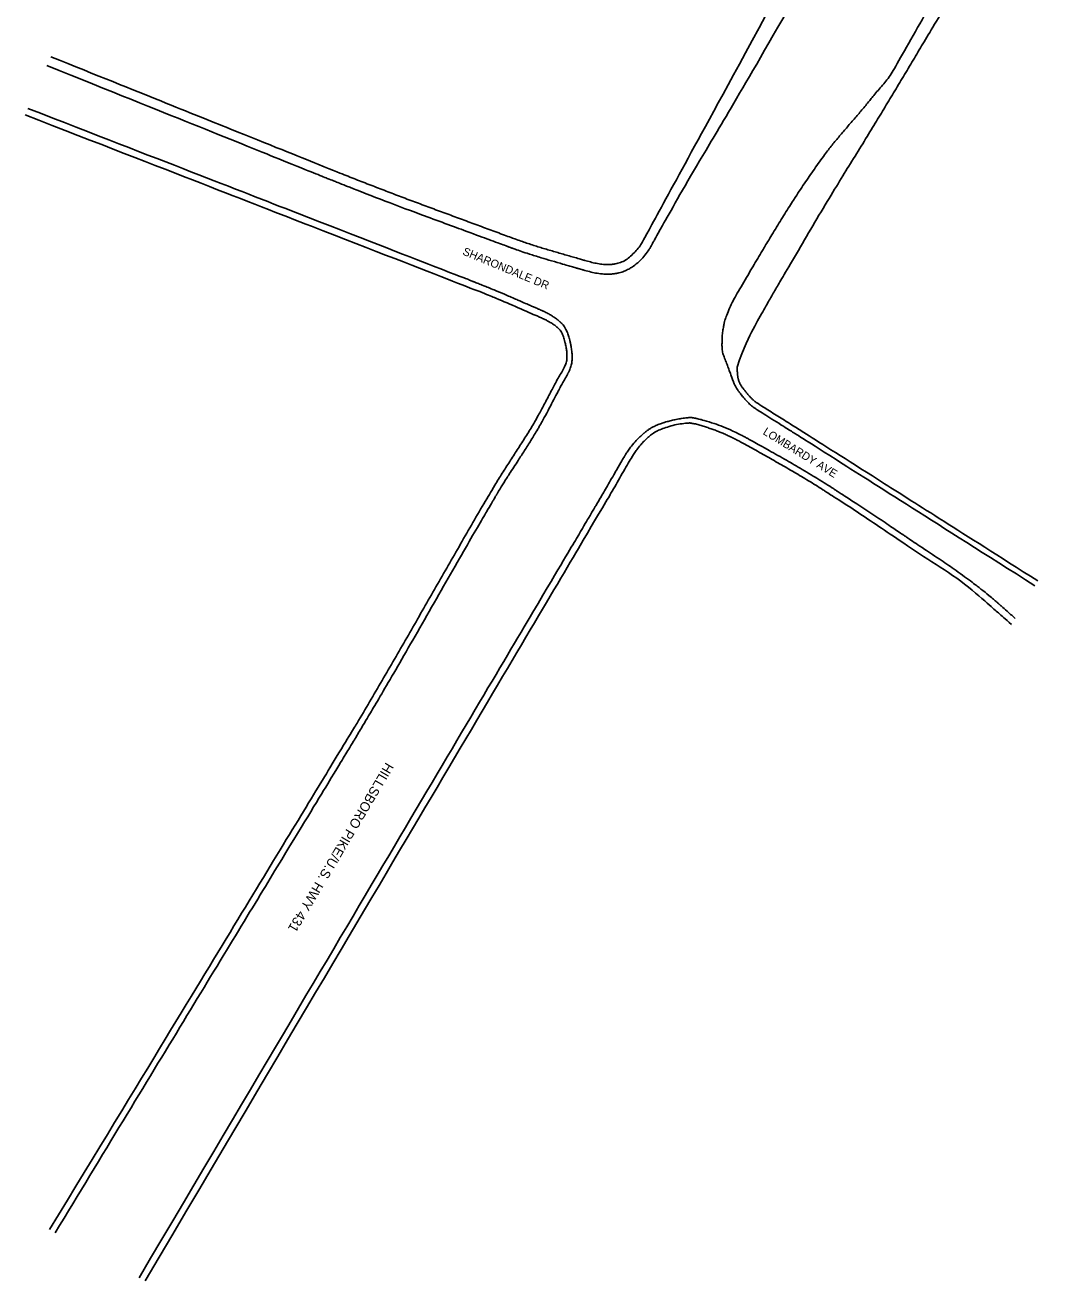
# Model space of a CAD drawing. Extents: x 1729281 to 1732101, y 650763 to 653805.
# Drawn here: x 1729590 to 1730235, y 651061 to 651845 of the extents above; entities that cross this region are included whole.
import ezdxf

# ---------------------------------------------------------------- set-up
doc = ezdxf.new("R2010")
doc.units = 0
for name, color, linetype in [('SURVEY - ROADSIDE BARRIERS with Text', 7, 'Continuous'), ('SURVEY - TRANSPORTATION - Roads', 7, 'Continuous'), ('SURVEY - TRANSPORTATION - Roads Text', 7, 'Continuous')]:
    doc.layers.add(name, color=color, linetype=linetype)

msp = doc.modelspace()

# ---------------------------------------------------------------- linework, layer by layer
at = {"layer": 'SURVEY - ROADSIDE BARRIERS with Text'}
for points in [[(1729607.28, 652582.79), (1729656.5, 652570.21), (1729705.61, 652557.15), (1729754.69, 652544), (1729803.78, 652530.84), (1729852.75, 652517.23), (1729901.76, 652503.78), (1729923.26, 652497.88), (1729944.71, 652491.85), (1729966.14, 652485.64), (1729976.27, 652482.71), (1729986.17, 652479.02), (1729995.91, 652474.96), (1730000.8, 652472.93), (1730005.64, 652470.81), (1730010.45, 652468.61), (1730015.28, 652466.4), (1730020.1, 652464.18), (1730024.89, 652461.88), (1730029.11, 652459.85), (1730033.28, 652457.72), (1730037.41, 652455.5), (1730041.51, 652453.29), (1730045.54, 652450.96), (1730049.52, 652448.54), (1730053.51, 652446.11), (1730057.45, 652443.62), (1730061.35, 652441.05), (1730065.28, 652438.46), (1730069.16, 652435.81), (1730073.02, 652433.1), (1730076.79, 652430.46), (1730080.48, 652427.72), (1730084.14, 652424.92), (1730087.78, 652422.14), (1730091.29, 652419.23), (1730094.75, 652416.24), (1730098.22, 652413.26), (1730101.53, 652410.13), (1730104.8, 652406.93), (1730108.11, 652403.69), (1730111.24, 652400.33), (1730114.27, 652396.83), (1730120.69, 652389.39), (1730126.62, 652381.63), (1730132.24, 652373.56), (1730137.84, 652365.51), (1730142.91, 652357.23), (1730147.82, 652348.73), (1730153.25, 652339.33), (1730158.14, 652329.79), (1730162.46, 652319.78), (1730167.07, 652309.1), (1730170.27, 652298.17), (1730173.35, 652286.9), (1730176.3, 652276.14), (1730179.69, 652265.38), (1730179.43, 652254.38), (1730179.05, 652238.66), (1730177.83, 652222.9), (1730176.7, 652207.18), (1730176.17, 652199.67), (1730175.69, 652192.16), (1730174.92, 652184.66), (1730172.45, 652160.83), (1730166.43, 652137.56), (1730159.58, 652114.52), (1730154.45, 652097.26), (1730149.17, 652080.18), (1730142.79, 652063.41), (1730133.99, 652040.24), (1730124.7, 652017.28), (1730116.01, 651994.07), (1730113.25, 651986.71), (1730110.5, 651979.34), (1730107.76, 651971.96), (1730105.02, 651964.59), (1730102.42, 651957.16), (1730099.69, 651949.77), (1730094.24, 651935.05), (1730088.32, 651920.44), (1730081.08, 651906.51), (1730070.13, 651885.43), (1730059.18, 651864.34), (1730048.23, 651843.25)], [(1730034.37, 651631.27), (1730038.78, 651643.98), (1730044.83, 651656.11), (1730051.49, 651667.81), (1730055.5, 651674.84), (1730059.55, 651681.84), (1730063.66, 651688.81), (1730073.99, 651706.34), (1730084.2, 651723.94), (1730094.73, 651741.35), (1730102.26, 651753.8), (1730110.03, 651766.09), (1730117.59, 651778.52), (1730123.75, 651788.66), (1730129.9, 651798.79), (1730136.01, 651808.95), (1730142.12, 651819.12), (1730148.15, 651829.33), (1730154.25, 651839.5), (1730163.39, 651854.75), (1730172.66, 651869.93), (1730181.9, 651885.14), (1730184.98, 651890.21), (1730188.11, 651895.24), (1730191.34, 651900.22), (1730194.52, 651905.11), (1730198.02, 651909.76), (1730201.62, 651914.35), (1730203.42, 651916.64), (1730205.27, 651918.89), (1730207.07, 651921.18), (1730208.87, 651923.48), (1730210.64, 651925.79), (1730212.41, 651928.1), (1730216.77, 651933.79), (1730220.59, 651939.87), (1730224.91, 651945.61), (1730227.32, 651948.8), (1730230.05, 651951.72), (1730233.01, 651954.44), (1730234.5, 651955.81), (1730236.07, 651957.04), (1730237.69, 651958.25), (1730239.34, 651959.47), (1730241.02, 651960.62), (1730242.77, 651961.69), (1730245.89, 651963.61), (1730249.11, 651965.23), (1730252.5, 651966.62), (1730255.86, 651967.99), (1730259.26, 651969.05), (1730262.77, 651969.91), (1730269.63, 651971.61), (1730276.5, 651972.86), (1730283.49, 651973.85), (1730291.08, 651974.92), (1730298.75, 651975.53), (1730306.35, 651975.28), (1730313.17, 651975.04), (1730320.01, 651974.17), (1730326.7, 651972.42), (1730334.32, 651970.42), (1730341.67, 651968), (1730349.21, 651965.98), (1730366.07, 651961.48), (1730382.84, 651957.15), (1730399.99, 651953.25), (1730412.36, 651950.43), (1730424.92, 651948.91), (1730437.49, 651948.6), (1730449.02, 651948.32), (1730460.62, 651948.91), (1730472.14, 651950.03), (1730480.98, 651950.89), (1730489.79, 651951.8), (1730498.56, 651953.25), (1730508.4, 651954.87), (1730518.17, 651956.64), (1730527.85, 651958.97), (1730538.72, 651961.58), (1730549.49, 651964.58), (1730560.35, 651967.19), (1730596.39, 651975.85), (1730632.48, 651984.17), (1730668.64, 651992.36), (1730684.27, 651995.91), (1730699.92, 651999.04), (1730715.78, 652001.66), (1730733.43, 652004.57), (1730751.19, 652006.36), (1730769, 652006.66), (1730780.51, 652006.85), (1730792.01, 652007.04), (1730803.52, 652007.24)], [(1729605.6, 651825.11), (1729663.95, 651801.64), (1729722.3, 651778.16), (1729780.65, 651754.68), (1729790.1, 651750.88), (1729799.58, 651747.17), (1729809.09, 651743.51), (1729818.59, 651739.85), (1729828.12, 651736.24), (1729837.66, 651732.7), (1729847.22, 651729.16), (1729856.77, 651725.62), (1729866.33, 651722.09), (1729875.89, 651718.56), (1729885.46, 651715.04), (1729895.03, 651711.52), (1729898.51, 651710.24), (1729902.02, 651709.04), (1729905.54, 651707.89), (1729909.07, 651706.74), (1729912.61, 651705.64), (1729916.17, 651704.6), (1729919.73, 651703.56), (1729923.29, 651702.52), (1729926.85, 651701.48), (1729930.41, 651700.45), (1729933.97, 651699.42), (1729937.53, 651698.39), (1729939.27, 651697.88), (1729941.02, 651697.4), (1729942.77, 651696.93), (1729944.53, 651696.44), (1729946.32, 651696.1), (1729948.14, 651695.8), (1729949.92, 651695.49), (1729951.72, 651695.36), (1729953.52, 651695.34), (1729954.4, 651695.32), (1729955.29, 651695.39), (1729956.17, 651695.46), (1729957.05, 651695.53), (1729957.91, 651695.67), (1729958.78, 651695.88), (1729962.44, 651696.8), (1729965.73, 651698.58), (1729968.57, 651701.25), (1729971.48, 651704), (1729973.82, 651706.91), (1729975.66, 651710.27), (1729999.85, 651754.6), (1730024.04, 651798.93), (1730048.23, 651843.25)], [(1729589.53, 651788.81), (1729682.94, 651752.5), (1729776.36, 651716.18), (1729869.77, 651679.87), (1729883.79, 651674.42), (1729897.54, 651668.35), (1729911.34, 651662.36), (1729913.33, 651661.49), (1729915.27, 651660.53), (1729917.19, 651659.49), (1729918.16, 651658.97), (1729919.05, 651658.33), (1729919.96, 651657.7), (1729920.92, 651657.04), (1729921.8, 651656.34), (1729922.65, 651655.52), (1729923.83, 651654.4), (1729924.73, 651653.1), (1729925.38, 651651.61), (1729926.01, 651650.15), (1729926.4, 651648.67), (1729926.76, 651647.13), (1729927.39, 651644.48), (1729927.9, 651641.83), (1729928.03, 651639.18), (1729928.16, 651636.63), (1729927.8, 651634.01), (1729926.58, 651631.58), (1729924.85, 651628.11), (1729922.96, 651625.17), (1729921.23, 651621.93), (1729917.28, 651614.55), (1729913.5, 651607.08), (1729909.44, 651599.77), (1729907.34, 651595.99), (1729905.12, 651592.29), (1729902.8, 651588.64), (1729900.48, 651584.99), (1729898.16, 651581.35), (1729895.82, 651577.71), (1729893.49, 651574.08), (1729891.12, 651570.46), (1729888.79, 651566.82), (1729886.46, 651563.19), (1729884.18, 651559.51), (1729881.99, 651555.79), (1729874.15, 651542.5), (1729866.39, 651529.17), (1729858.71, 651515.78), (1729851.03, 651502.4), (1729843.39, 651489), (1729835.7, 651475.62), (1729828.02, 651462.24), (1729820.32, 651448.86), (1729812.57, 651435.52), (1729804.81, 651422.18), (1729796.93, 651408.92), (1729788.92, 651395.73), (1729727.55, 651294.68), (1729666.18, 651193.63), (1729604.8, 651092.58)], [(1730034.37, 651631.27), (1730034.41, 651630.17), (1730034.47, 651629.07), (1730034.55, 651627.97), (1730034.59, 651627.42), (1730034.65, 651626.87), (1730034.71, 651626.32), (1730034.77, 651625.77), (1730034.84, 651625.23), (1730034.93, 651624.68), (1730035.05, 651623.91), (1730035.26, 651623.16), (1730035.54, 651622.43), (1730035.82, 651621.69), (1730036.16, 651620.99), (1730036.56, 651620.32), (1730036.98, 651619.63), (1730037.4, 651618.96), (1730037.88, 651618.32), (1730038.36, 651617.66), (1730038.86, 651617.03), (1730039.36, 651616.39), (1730040.56, 651614.9), (1730041.78, 651613.45), (1730043.1, 651612.07), (1730044.39, 651610.72), (1730045.82, 651609.5), (1730047.38, 651608.51), (1730055.71, 651603.24), (1730064.07, 651598.05), (1730072.39, 651592.78), (1730122.35, 651561.1), (1730172.3, 651529.43), (1730222.26, 651497.75)], [(1730205.93, 651470.44), (1730201.61, 651474.24), (1730197.3, 651478.05), (1730192.99, 651481.85), (1730174.51, 651498.15), (1730153.43, 651511.24), (1730132.99, 651525.01), (1730119.51, 651534.08), (1730106.04, 651543.14), (1730092.36, 651551.9), (1730087.94, 651554.73), (1730083.51, 651557.54), (1730079.02, 651560.26), (1730074.55, 651562.98), (1730070.05, 651565.66), (1730065.51, 651568.28), (1730060.96, 651570.91), (1730056.4, 651573.5), (1730051.83, 651576.09), (1730047.23, 651578.69), (1730042.61, 651581.25), (1730037.98, 651583.8), (1730035.42, 651585.21), (1730032.81, 651586.53), (1730030.18, 651587.81), (1730027.57, 651589.09), (1730024.89, 651590.21), (1730022.17, 651591.28), (1730019.47, 651592.35), (1730016.72, 651593.24), (1730013.94, 651594.14), (1730011.16, 651595.04), (1730008.35, 651595.79), (1730005.48, 651596.31), (1730004.87, 651596.42), (1730004.23, 651596.37), (1730003.61, 651596.31), (1729998.89, 651595.84), (1729994.27, 651595), (1729989.68, 651593.45), (1729986.17, 651592.26), (1729982.92, 651590.74), (1729980.03, 651588.45), (1729978.88, 651587.53), (1729977.83, 651586.55), (1729976.8, 651585.52), (1729975.8, 651584.51), (1729974.8, 651583.52), (1729973.88, 651582.42), (1729972.07, 651580.25), (1729970.39, 651578), (1729968.96, 651575.58), (1729962.59, 651564.77), (1729956.42, 651553.85), (1729950.03, 651543.06), (1729854.85, 651382.23), (1729759.66, 651221.41), (1729664.47, 651060.59)]]:
    msp.add_open_spline(points, degree=3, dxfattribs=at)
at = {"layer": 'SURVEY - TRANSPORTATION - Roads'}
for points in [[(1730032.07, 651621.98), (1730031.23, 651624.36), (1730030.38, 651626.73), (1730029.53, 651629.11), (1730028.41, 651632.25), (1730027.12, 651635.2), (1730026, 651638.46), (1730025.04, 651641.26), (1730024.93, 651644.14), (1730024.96, 651646.98), (1730025.01, 651650.3), (1730025.35, 651653.64), (1730026, 651656.96), (1730026.37, 651658.81), (1730026.78, 651660.6), (1730027.46, 651662.36), (1730029.24, 651667.04), (1730031.17, 651671.58), (1730033.65, 651675.88), (1730036.91, 651681.51), (1730040.18, 651687.14), (1730043.5, 651692.74), (1730046.5, 651697.81), (1730049.49, 651702.88), (1730052.52, 651707.94), (1730058.25, 651717.53), (1730064.16, 651727), (1730070.18, 651736.42), (1730073.18, 651741.13), (1730076.32, 651745.75), (1730079.48, 651750.36), (1730082.64, 651754.97), (1730085.87, 651759.53), (1730089.21, 651764.02), (1730091.42, 651767), (1730093.69, 651769.94), (1730096.07, 651772.79), (1730098.46, 651775.64), (1730100.86, 651778.47), (1730103.27, 651781.29), (1730105.69, 651784.11), (1730108.13, 651786.91), (1730110.55, 651789.73), (1730112.97, 651792.55), (1730115.3, 651795.43), (1730117.65, 651798.31), (1730123.1, 651804.97), (1730128.95, 651811.41), (1730133.23, 651818.88), (1730144.4, 651838.38), (1730155.47, 651857.93), (1730166.57, 651877.47), (1730172.63, 651888.13), (1730178.68, 651898.81), (1730184.74, 651909.47), (1730188.03, 651915.24), (1730191.75, 651920.76), (1730195.69, 651926.12), (1730197.66, 651928.81), (1730199.72, 651931.43), (1730201.79, 651934.04), (1730203.87, 651936.67), (1730205.98, 651939.26), (1730208.16, 651941.81), (1730212.34, 651946.72), (1730217.06, 651951.03), (1730221.97, 651955.27), (1730227.62, 651960.14), (1730233.66, 651964.21), (1730240.14, 651968), (1730247.7, 651972.41), (1730255.41, 651975.89), (1730263.76, 651978.54), (1730272.62, 651981.36), (1730281.54, 651983.1), (1730290.66, 651984), (1730298.14, 651984.74), (1730305.72, 651985.06), (1730313.19, 651984.36), (1730320.14, 651983.71), (1730327.13, 651982.89), (1730333.9, 651981.09), (1730341.07, 651979.18), (1730348.19, 651977.18), (1730355.34, 651975.27), (1730366.84, 651972.2), (1730378.31, 651969.08), (1730389.87, 651966.18), (1730396.89, 651964.42), (1730404.11, 651963.76), (1730411.31, 651962.91), (1730420.99, 651961.76), (1730430.67, 651960.89), (1730440.38, 651960.36), (1730450.87, 651959.8), (1730461.42, 651959.96), (1730471.91, 651960.75), (1730482.41, 651961.54), (1730492.94, 651962.62), (1730503.16, 651965.11), (1730520.01, 651969.22), (1730536.84, 651973.34), (1730553.68, 651977.48), (1730573.36, 651982.31), (1730593.04, 651987.17), (1730612.73, 651992), (1730632.69, 651996.89), (1730652.86, 652000.8), (1730673.06, 652004.73), (1730690.41, 652008.11), (1730707.83, 652010.74), (1730725.39, 652013.09), (1730738.29, 652014.82), (1730751.2, 652016.39), (1730764.18, 652016.46), (1730777.44, 652016.52), (1730790.7, 652016.41), (1730803.96, 652016.18)], [(1729603.17, 651819.62), (1729644.86, 651802.85), (1729697.28, 651781.76), (1729755.04, 651758.51), (1729771.12, 651752.04), (1729779.16, 651748.81), (1729781.85, 651747.73), (1729787.23, 651745.59), (1729811.48, 651736.01), (1729835.87, 651726.93), (1729868.41, 651714.93), (1729879.26, 651710.95), (1729890.78, 651706.7), (1729891.45, 651706.45), (1729892.47, 651706.07), (1729892.8, 651705.95), (1729893.5, 651705.69), (1729895.24, 651705.05), (1729899.77, 651703.45), (1729903.97, 651702.08), (1729912.36, 651699.44), (1729917.95, 651697.81), (1729926.29, 651695.4), (1729929.07, 651694.6), (1729932.52, 651693.6), (1729933.55, 651693.3), (1729934.58, 651693), (1729935.27, 651692.8), (1729935.61, 651692.7), (1729937.37, 651692.18), (1729938.83, 651691.76), (1729943.38, 651690.55), (1729946.62, 651689.83), (1729951.71, 651689.35), (1729953.45, 651689.29), (1729956.1, 651689.42), (1729957, 651689.5), (1729958.34, 651689.69), (1729958.79, 651689.77), (1729959.47, 651689.9), (1729959.69, 651689.94), (1729960.14, 651690.04), (1729960.38, 651690.1), (1729962.49, 651690.62), (1729964.26, 651691.31), (1729967.59, 651693.01), (1729969.15, 651694.02), (1729973.5, 651697.37), (1729975.99, 651700.04), (1729979.1, 651704.31), (1729980.03, 651705.78), (1729980.96, 651707.46), (1729981.04, 651707.61), (1729981.21, 651707.92), (1729981.47, 651708.4), (1729982.07, 651709.51), (1729983.98, 651712.99), (1730008.94, 651757.36), (1730033.64, 651797.73), (1730069.36, 651859.94)], [(1729591.33, 651792.87), (1729676.41, 651759.8), (1729766.94, 651724.6), (1729858.84, 651688.88), (1729866.34, 651685.97), (1729868.38, 651685.17), (1729869.4, 651684.77), (1729869.75, 651684.64), (1729870.44, 651684.37), (1729873.54, 651683.15), (1729876.62, 651681.91), (1729884.81, 651678.54), (1729890.22, 651676.23), (1729898.3, 651672.74), (1729900.98, 651671.58), (1729905.01, 651669.83), (1729907.02, 651668.96), (1729909.37, 651667.94), (1729910.46, 651667.47), (1729910.88, 651667.29), (1729911.05, 651667.22), (1729911.14, 651667.18), (1729911.41, 651667.07), (1729911.58, 651666.99), (1729913.18, 651666.29), (1729914.61, 651665.61), (1729917.51, 651664.07), (1729918.96, 651663.2), (1729921.13, 651661.68), (1729921.85, 651661.13), (1729922.92, 651660.26), (1729923.27, 651659.96), (1729923.71, 651659.56), (1729923.81, 651659.48), (1729923.91, 651659.39), (1729923.93, 651659.37), (1729923.94, 651659.36), (1729923.98, 651659.32), (1729924.07, 651659.24), (1729924.38, 651658.94), (1729924.66, 651658.67), (1729925.71, 651657.55), (1729926.41, 651656.6), (1729927.56, 651654.68), (1729928.02, 651653.72), (1729928.77, 651651.86), (1729929.06, 651650.96), (1729929.54, 651649.25), (1729929.73, 651648.44), (1729930.26, 651646.19), (1729930.62, 651644.54), (1729931.15, 651641.05), (1729931.33, 651639.2), (1729931.28, 651635.32), (1729931.04, 651633.28), (1729930.1, 651630.19), (1729929.68, 651629.16), (1729929.13, 651628.13), (1729929.12, 651628.11), (1729929.1, 651628.07), (1729929.07, 651628.01), (1729928.99, 651627.86), (1729928.83, 651627.56), (1729928.51, 651626.97), (1729928.24, 651626.47), (1729927.32, 651624.81), (1729926.58, 651623.52), (1729925.16, 651621), (1729924.46, 651619.76), (1729923.73, 651618.39), (1729923.64, 651618.23), (1729923.47, 651617.91), (1729923.22, 651617.43), (1729922.63, 651616.32), (1729922.12, 651615.36), (1729919.09, 651609.57), (1729916.41, 651604.32), (1729912.81, 651597.78), (1729912.08, 651596.47), (1729910.6, 651593.87), (1729909.84, 651592.58), (1729907.55, 651588.73), (1729906, 651586.2), (1729901.27, 651578.67), (1729898.05, 651573.75), (1729891.71, 651563.95), (1729888.59, 651559.08), (1729885.26, 651553.55), (1729884.89, 651552.93), (1729884.35, 651552.01), (1729884.16, 651551.69), (1729883.79, 651551.06), (1729882.86, 651549.49), (1729880.45, 651545.4), (1729866.44, 651521.47), (1729841.8, 651478.31), (1729818.47, 651437.66), (1729803.57, 651412.42), (1729799.07, 651404.86), (1729794.53, 651397.32), (1729791.49, 651392.3), (1729789.97, 651389.8), (1729782.38, 651377.3), (1729752.01, 651327.29), (1729691.96, 651228.43), (1729637.99, 651139.56), (1729608.31, 651090.7)], [(1730032.07, 651621.98), (1730032.17, 651621.72), (1730032.27, 651621.47), (1730032.74, 651620.39), (1730033.14, 651619.61), (1730034.4, 651617.44), (1730035.31, 651616.19), (1730036.61, 651614.51), (1730037.02, 651613.99), (1730037.87, 651612.93), (1730038.31, 651612.4), (1730039.68, 651610.79), (1730040.66, 651609.71), (1730042.82, 651607.62), (1730044, 651606.61), (1730045.65, 651605.45), (1730045.98, 651605.23), (1730046.35, 651604.99), (1730046.37, 651604.98), (1730046.41, 651604.96), (1730046.45, 651604.93), (1730046.57, 651604.85), (1730046.8, 651604.71), (1730047.53, 651604.24), (1730052.45, 651601.14), (1730057.23, 651598.15), (1730063.58, 651594.17), (1730066.76, 651592.17), (1730069.92, 651590.17), (1730072.03, 651588.84), (1730073.09, 651588.17), (1730091.06, 651576.77), (1730139.83, 651545.85), (1730188.6, 651514.92), (1730220.46, 651494.72)], [(1730208.22, 651474.27), (1730205.96, 651476.25), (1730202.8, 651479.04), (1730199.41, 651482.03), (1730198.28, 651483.03), (1730197.83, 651483.43), (1730197.6, 651483.63), (1730196.9, 651484.25), (1730194.56, 651486.29), (1730192.19, 651488.28), (1730186.43, 651492.96), (1730182.52, 651495.96), (1730170.64, 651504.71), (1730162.52, 651510.19), (1730150.4, 651518.28), (1730146.36, 651520.96), (1730141.36, 651524.32), (1730140.36, 651525), (1730138.36, 651526.35), (1730137.38, 651527.02), (1730134.36, 651529.07), (1730124.31, 651535.89), (1730114.19, 651542.57), (1730104.04, 651549.2), (1730100.99, 651551.18), (1730097.94, 651553.16), (1730095.9, 651554.48), (1730094.87, 651555.15), (1730089.72, 651558.44), (1730085.57, 651561.01), (1730073.08, 651568.57), (1730064.68, 651573.42), (1730051.96, 651580.58), (1730047.7, 651582.95), (1730042.89, 651585.61), (1730042.29, 651585.95), (1730041.69, 651586.28), (1730041.55, 651586.35), (1730041.49, 651586.39), (1730041.28, 651586.51), (1730040.86, 651586.74), (1730039.33, 651587.57), (1730035.67, 651589.49), (1730032.23, 651591.13), (1730025.25, 651594.21), (1730020.47, 651596), (1730013.1, 651598.18), (1730010.61, 651598.82), (1730007.93, 651599.41), (1730007.7, 651599.46), (1730007.42, 651599.52), (1730007.3, 651599.55), (1730007.26, 651599.56), (1730007.25, 651599.56), (1730007.24, 651599.56), (1730007.22, 651599.56), (1730007.18, 651599.57), (1730007.09, 651599.59), (1730007, 651599.61), (1730006.1, 651599.77), (1730005.37, 651599.78), (1730004.49, 651599.74), (1730004.24, 651599.72), (1730003.79, 651599.68), (1730003.61, 651599.66), (1730003.12, 651599.61), (1730001.5, 651599.43), (1729999.89, 651599.2), (1729996.04, 651598.55), (1729993.48, 651598), (1729990.29, 651597.12), (1729989.49, 651596.89), (1729988.69, 651596.64), (1729988.37, 651596.54), (1729988.2, 651596.49), (1729987.71, 651596.33), (1729987.38, 651596.21), (1729985.72, 651595.64), (1729984.39, 651595.11), (1729981.74, 651593.85), (1729980.43, 651593.12), (1729978.51, 651591.83), (1729977.88, 651591.36), (1729977.1, 651590.75), (1729976.95, 651590.62), (1729976.64, 651590.36), (1729976.52, 651590.26), (1729976.13, 651589.92), (1729975.87, 651589.7), (1729973.54, 651587.66), (1729971.62, 651585.74), (1729968.08, 651581.64), (1729966.46, 651579.46), (1729964.84, 651576.86), (1729964.62, 651576.49), (1729964.4, 651576.12), (1729964.31, 651575.98), (1729964.27, 651575.91), (1729964.16, 651575.72), (1729963.77, 651575.06), (1729962.77, 651573.36), (1729959.41, 651567.58), (1729953.96, 651558.15), (1729949.13, 651549.81), (1729946.07, 651544.62), (1729945.46, 651543.59), (1729944.23, 651541.51), (1729942.38, 651538.38), (1729935.6, 651526.93), (1729919.58, 651499.87), (1729826.74, 651343), (1729738.82, 651194.46), (1729660.76, 651062.58)]]:
    msp.add_open_spline(points, degree=3, dxfattribs=at)

# ---------------------------------------------------------------- texts
at = {"layer": 'SURVEY - TRANSPORTATION - Roads Text'}
for s, height, rotation, p in [('SHARONDALE DR', 5, 337.52494, (1729862.48, 651701.66)), ('LOMBARDY AVE', 5, 328.31725, (1730050.1, 651589.64)), ('HILLSBORO PIKE/U.S. HWY 431', 6, 239.43306, (1729814.98, 651384.78))]:
    msp.add_text(s, height=height, rotation=rotation, dxfattribs=at).set_placement(p)

doc.saveas('drawing.dxf')
